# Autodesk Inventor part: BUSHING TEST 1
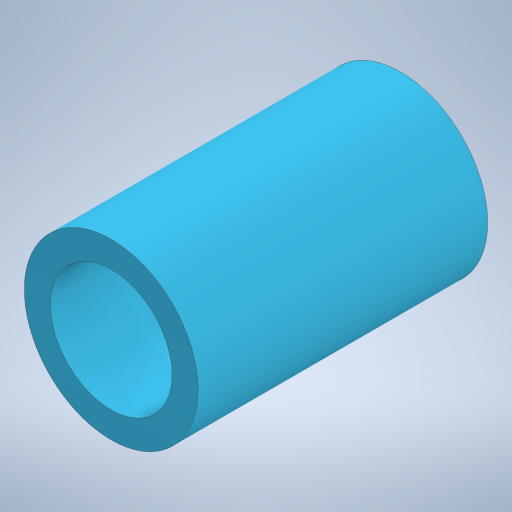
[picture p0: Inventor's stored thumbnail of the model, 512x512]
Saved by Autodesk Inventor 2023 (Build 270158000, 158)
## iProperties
Created: 2025-07
Part Number: BUSHING TEST 1
Material: Generic
Document SubType Name: Modeling
Designer: erjon
Density: 1 g/cm^3
Appearance: Default
Author: erjon
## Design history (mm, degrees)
sketch "Sketch1"
  geometry: C1 r 6 at (0, 0); C2 r 4.2 at (0, 0); 1 further point
  constraints: 2 centre point, 2 coincident
  dimensions: "d0" = 12 diameter of C1; "d1" = 8.4 diameter of C2
extrude "Extrusion1" new body sketch "Sketch1" distance "d2" = 20; taper "d3" = 0 deg
body "Solid1"
